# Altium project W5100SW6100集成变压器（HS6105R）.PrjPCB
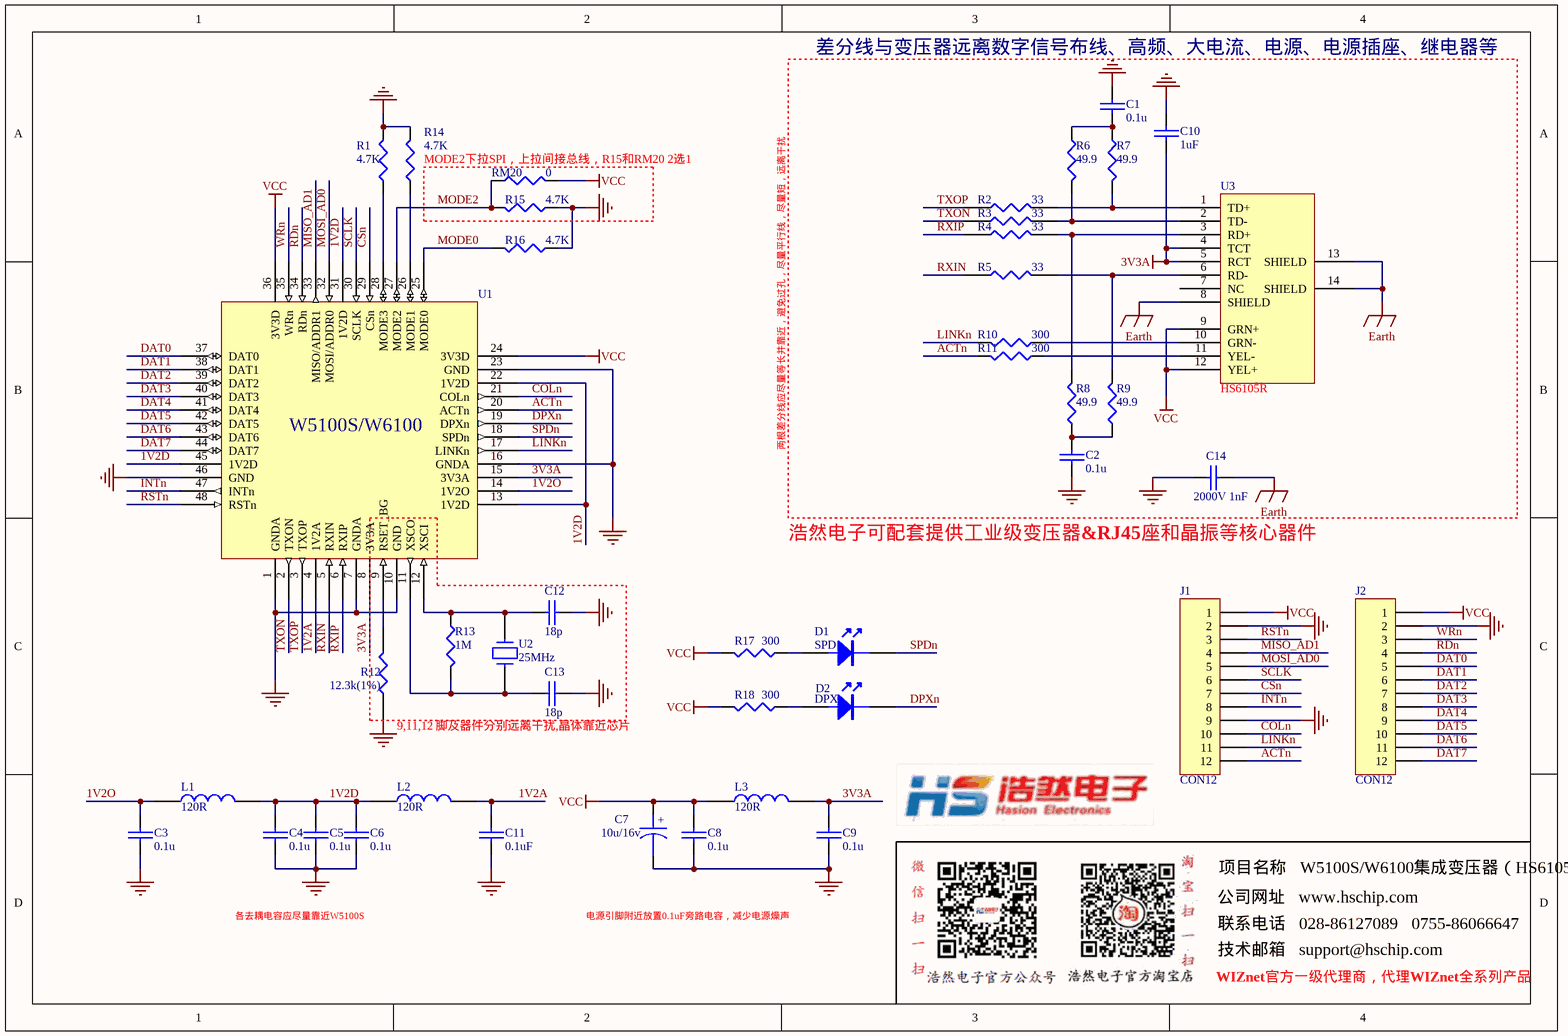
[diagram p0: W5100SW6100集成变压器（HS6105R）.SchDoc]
1 sheet, 43 parts. Net scope: global (net labels, ports and power ports of the same name join across sheets).

## Sheet W5100SW6100集成变压器（HS6105R）.SchDoc
size A4; SheetNumber: 0; SheetTotal: 0; PageSetup: Record=PageOptions?CenterHorizontal=True?CenterVertical=True?PrintScale=1.00?XCorrection=1.00?YCorrection=1.00?PrintKind=0?BorderSize=5000000?LeftOffset=0?BottomOffset=0?Orientation=2?PaperLength=1000?PaperWidth=1000?Scale=100?PaperSource=7?PrintQuality=-4?MediaType=1?DitherType=10?PaperKind=A4?PrintScaleMode=1

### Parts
C1  0.1u  [0603]
C2  0.1u  [0603]
C3  0.1u  [0603]
C4  0.1u  [0603]
C5  0.1u  [0603]
C6  0.1u  [0603]
C7  10u/16v  [3216]
C8  0.1u  [0603]
C9  0.1u  [0603]
C10  1uF  [0603]
C11  0.1uF  [0603]
C12  18p  [0603]
C13  18p  [0603]
C14  2000V 1nF  [3216]
D1  SPD
D2  DPX
J1  CON12  [SIP12]
J2  CON12  [SIP12]
L1  120R  [0603]
L2  120R  [0603]
L3  120R  [0603]
R1  4.7K  [0603]
R2  33  [0603]
R3  33  [0603]
R4  33  [0603]
R5  33  [0603]
R6  49.9  [0603]
R7  49.9  [0603]
R8  49.9  [0603]
R9  49.9  [0603]
R10  300  [0603]
R11  300  [0603]
R12  12.3k(1%)  [0603]
R13  1M  [0603]
R14  4.7K  [0603]
R15  4.7K  [0603]
R16  4.7K  [0603]
R17  300  [0603]
R18  300  [0603]
RM20  0  [0603]
U1  W5100S/W6100  [LQFP48-W5500/W5100S/W6100/C8T6]
U2  25MHz  [XTAL-49S]
U3  HS6105R  [RJ45-HS6105R]

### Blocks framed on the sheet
差分线与变压器远离数字信号布线、高频、大电流、电源、电源插座、继电器等: C1 C2 C10 C14 R2-R11 U3
MODE2下拉SPI，上拉间接总线，R15和RM20 2选1: R15 RM20

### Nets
3V3A: C9.1 C10.1 L3.2 U1.8(3V3A) U1.15(3V3A) U3.4(TCT) U3.5(RCT)
Earth: C14.1 U3.8(SHIELD) U3.13(SHIELD) U3.14(SHIELD)
GND: C1.2 C2.2 C3.2 C4.2 C5.2 C6.2 C7.2 C8.2 C9.2 C10.2 C11.1 C12.2 C13.2 C14.2 J1.2 J1.9 J2.2 R1.2 R12.1 R14.2 R15.1 R16.1 U1.1(GNDA) U1.7(GNDA) U1.10(GND) U1.16(GNDA) U1.23(GND) U1.46(GND)
VCC: C7.1 C8.1 J1.1 J2.1 L3.1 R17.2 R18.2 RM20.2 U1.24(3V3D) U1.36(3V3D) U3.9(GRN+) U3.12(YEL+)
1V2A: C11.2 L2.2 U1.4(1V2A)
1V2D: C4.1 C5.1 C6.1 L1.2 L2.1 U1.13(1V2D) U1.22(1V2D) U1.31(1V2D) U1.45(1V2D)
1V2O: C3.1 L1.1 U1.14(1V2O)
ACTn: J1.12 R11.2 U1.20(ACTn)
COLn: J1.10 U1.21(COLn)
CSn: J1.7 U1.29(CSn)
DAT0: J2.5 U1.37(DAT0)
DAT1: J2.6 U1.38(DAT1)
DAT2: J2.7 U1.39(DAT2)
DAT3: J2.8 U1.40(DAT3)
DAT4: J2.9 U1.41(DAT4)
DAT5: J2.10 U1.42(DAT5)
DAT6: J2.11 U1.43(DAT6)
DAT7: J2.12 U1.44(DAT7)
DPXn: D2.K U1.19(DPXn)
INTn: J1.8 U1.47(INTn)
LINKn: J1.11 R10.2 U1.17(LINKn)
MISO_AD1: J1.4 U1.33(MISO/ADDR1)
MODE0: R16.2 U1.25(MODE0)
MODE2: R15.2 RM20.1 U1.27(MODE2)
MOSI_AD0: J1.5 U1.32(MOSI/ADDR0)
RDn: J2.4 U1.34(RDn)
RSTn: J1.3 U1.48(RSTn)
RXIN: R5.1 U1.5(RXIN)
RXIP: R4.1 U1.6(RXIP)
SCLK: J1.6 U1.30(SCLK)
SPDn: D1.K U1.18(SPDn)
TXON: R3.1 U1.2(TXON)
TXOP: R2.1 U1.3(TXOP)
WRn: J2.3 U1.35(WRn)
NetC1_1: C1.1 R6.1 R7.1
NetC2_1: C2.1 R8.1 R9.1
NetC12_1: C12.1 R13.1 U1.12(XSCI) U2.2
NetC13_1: C13.1 R13.2 U1.11(XSCO) U2.1
NetD1_A: D1.A R17.1
NetD2_A: D2.A R18.1
NetR1_1: R1.1 U1.28(MODE3)
NetR2_2: R2.2 R7.2 U3.1(TD+)
NetR3_2: R3.2 R6.2 U3.2(TD-)
NetR4_2: R4.2 R8.2 U3.3(RD+)
NetR5_2: R5.2 R9.2 U3.6(RD-)
NetR10_1: R10.1 U3.10(GRN-)
NetR11_1: R11.1 U3.11(YEL-)
NetR12_2: R12.2 U1.9(RSET_BG)
NetR14_1: R14.1 U1.26(MODE1)

Not connected (* = marked no-connect by the designer): U3 7(NC)

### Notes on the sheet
- 两根差分线应尽量等长并靠近，避免过孔，尽量平行线，尽量短，远离干扰
- 9,11,12 脚及器件分别远离干扰,晶体靠近芯片
- 各去耦电容应尽量靠近W5100S
- 电源引脚附近放置0.1uF旁路电容，减少电源燥声
- 公司网址   www.hschip.com
- 项目名称   W5100S/W6100集成变压器（HS6105R）
- WIZnet官方一级代理商，代理WIZnet全系列产品
- 联系电话   028-86127089   0755-86066647
- 技术邮箱   support@hschip.com
- Labels drawn without touching a wire or pin: 浩然电子可配套提供工业级变压器&RJ45座和晶振等核心器件

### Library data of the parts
C1-C6 C8-C14 = CAP: Capacitor
C7 = CAPACITOR POL: Capacitor
D1 D2 = LED
J1 J2 = CON12: Connector
L1-L3 = INDUCTOR
R1-R18 RM20 = RES1
U1 = W5100S
U2 = CRYSTAL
